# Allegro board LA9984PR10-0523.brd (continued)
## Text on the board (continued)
COMPVAL_TYPE_TOP: FIGURE | SIZE | 8.0 | 10.0 | 22.0 | 28.0 | 35.0 | 36.0 | 39.0 | 91.0 | 110.0 | 118.0 | 130.0 | 138.0 | 146.0 | 31.0 | 40.0 | 43.0 | 47.0 | 63.0 | 71.0 | 197.0 | 28.0x16.0 | 59.0x24.0 | 63.0x28.0 | 71.0x20.0 | 71.0x31.0 | 79.0x31.0 | 87.0x43.0 | 91.0x35.0 | 94.0x39.0 | 110.0x39.0 | 197.0x118.0 | DRILL CHART: TOP to BOTTOM | ALL UNITS ARE IN MILS | PLATED | NON-PLATED | QTY | 4885 | 690 | 19 | 40 | 8 | 4 | 9 | 2 | 1 | 3 | 5 | 26 | 7
User.32: 147.27 | 106.75 | 104.75 | 82.95 | 63.71 | 46.11 | 28.5 | 4.59 | 91 | 0 | 23.25 | 33.53 | 185.3 | 156.45 | 217.42 | 213.77 | 212.83 | 198.44 | 209.85 | 157.58 | 132.9 | 52.13 | 14.6 | Top View
User.33: 106.23 | 15.73 | 68.04 | 20.16 | 175 | 0 | Card reader SMT direction | 2.39 | 55.01 | 88.3 | 99.8 | 104.75 | 174 | 183.35 | Bottom View
User.34: Top View
User.35: Bottom View
User.36: 2 | 2.8 | n | 8 | 3.7 | 9 | 6 | 3.3 | 3.5 | 5 | 1.5 | R | Top View
User.37: 115.7 | 21.08 | 12.5 | 11.5 | 106 | 181.8 | 4 | 0 | 91 | 78 | 5.4 | 164.7 | 163.2 | 151.4 | 141.1 | 68.61 | 125.66 | 117.35 | 100.26 | 203.3 | 198.28 | 193 | 161.57 | 144.4 | 129.45 | 97.6 | 84 | 71.9 | 43 | 21.1 | 0.65 | 5.1 | 5.2 | 6.7 | Bottom View
User.38: WHITE PAINT | LABEL LOCATION WHITE PAINT | Top View
User.39: WHITE PAINT FOR STAND OFF | WHITE PAINT FOR MYLAR LOCATION | Bottom View
User.40: 148.62 | 156.4 | 131.7 | 115.5 | 87.54 | 71.26 | 66.95 | 53.45 | 49.35 | 35.85 | 31.81 | 18.21 | 13.29 | 92.5 | 5.44 | 117 | 108 | 1.1 | 0 | 5.4 | 9.08 | 5.08 | 187.7 | 186.7 | 177.7 | 176.2 | 86.05 | Top View
User.41: 147.27 | 106.75 | 104.75 | 82.95 | 63.71 | 46.11 | 28.5 | 4.59 | 91 | 0 | 23.25 | 33.53 | 185.3 | 156.45 | 217.42 | 213.77 | 212.83 | 198.44 | 209.85 | 157.58 | 132.9 | 52.13 | 14.6 | Top View
User.42: 0 | 175 | 20.16 | 68.04 | 16.94 | 106.23 | Card reader SMT direction | 183.35 | 174 | 104.75 | 100.1 | 88.3 | 55.01 | 2.39 | Bottom View
User.43: Top View
User.44: Bottom View
User.45: WHITE PAINT | 148.62 | 156.4 | 131.7 | 115.5 | 87.54 | 71.26 | 66.95 | 53.45 | 49.35 | 35.85 | 31.81 | 18.21 | 13.29 | 92.5 | 5.44 | 117 | 108 | 1.1 | 2 | 0 | 5.4 | 9.08 | 5.08 | 187.7 | 186.7 | 177.7 | 176.2 | 86.05 | 115.7 | 21.08 | 12.5 | 11.5 | 106 | 181.8 | 4 | 91 | 78 | 164.7 | 163.2 | 151.4 | 141.1 | 68.61 | 125.66 | 117.35 | 100.26 | LABEL LOCATION WHITE PAINT | WHITE PAINT FOR STAND OFF | WHITE PAINT FOR MYLAR LOCATION | 2.8 | n | 8 | 3.7 | 9 | 6 | 3.3 | 3.5 | 5 | 203.3 | 198.28 | 193 | 161.57 | 144.4 | 129.45 | 97.6 | 84 | 71.9 | 43 | 21.1 | 0.65 | 5.1 | 5.2 | 6.7 | 1.5 | R | Top View | Bottom View
